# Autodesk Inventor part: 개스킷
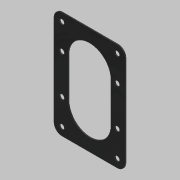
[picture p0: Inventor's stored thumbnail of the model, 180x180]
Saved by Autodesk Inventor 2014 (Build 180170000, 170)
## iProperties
Created: 2019-03
Part Number: 개스킷
Material: 고무
Document SubType Name: Modeling
Designer: mduedu
Density: 1 g/cm^3
Appearance: 고무 - 검은색 - 버전 1.1
Author: mduedu
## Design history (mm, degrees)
sketch "스케치1"
  geometry: L1 (-60, 40)-(60, 40); L2 (60, 40)-(60, -40); L3 (60, -40)-(-60, -40); L4 (-60, -40)-(-60, 40); L5 (-60, 40)-(60, -40); L6 (60, 40)-(-60, -40); 1 further point
  constraints: 12 end point, 2 midpoint, 2 parallel, 1 horizontal, 1 perpendicular
  dimensions: "d21" = 120 distance of L2.end L3.end; "d22" = 80 distance of L1.end L2.end
extrude "돌출1" new body sketch "스케치1" distance "d3" = 1; taper "d4" = 0 deg
fillet "모깎기1" dims "d5" = 9
sketch "스케치2" dims "d6" = 48
  geometry: L1 (-24, -22)-(24, -22); L2 (24, -22)-(24, 22); L3 (24, 22)-(-24, 22); L4 (-24, 22)-(-24, -22); L5 (-24, -22)-(24, 22); L6 (24, -22)-(-24, 22); 3 further points
  constraints: 12 end point, 4 midpoint, 2 horizontal alignment, 2 parallel, 1 horizontal, 1 perpendicular, 4 other
  dimensions: "d8" = 22 distance from line of L3 point (0, 0)
extrude "돌출2" cut sketch "스케치2" stored distance "d9" = 1; taper "d10" = 0 deg
sketch "스케치3"
  geometry: L1 (-24, -22)-(-24, 22) reference; L2 (24, 22)-(24, -22) reference; L3 (40, -51)-(40, 51) reference; L4 (31, 60)-(-31, 60) reference; L5 (-40, 51)-(-40, -51) reference; L6 (-31, -60)-(31, -60) reference; L7 (-31, 51)-(31, 51); L8 (31, 51)-(31, -51); L9 (31, -51)-(-31, -51); L10 (-31, -51)-(-31, 51); A1 r 24 centre (0, 22) between (24, 22) and (-24, 22) reference; A2 r 24 centre (0, -22) between (-24, -22) and (24, -22) reference; A3 r 9 centre (31, -51) between (31, -60) and (40, -51) reference; A4 r 9 centre (31, 51) between (40, 51) and (31, 60) reference; A5 r 9 centre (-31, 51) between (-31, 60) and (-40, 51) reference; A6 r 9 centre (-31, -51) between (-40, -51) and (-31, -60) reference; 9 further points
  constraints: 8 end point, 4 coincident, 4 horizontal alignment, 4 point on line, 2 parallel, 1 horizontal, 1 perpendicular
  dimensions: "d23" = 102 distance between parallel lines of L9 L7 (derived); "d24" = 29 distance from line of point (-31, 22) L7 (derived); "d25" = 29 distance from line of point (-31, -22) L9 (derived)
hole "구멍1" sketch "스케치3" at (-31, 51), (31, 51), (31, -51), (-31, -51), (-31, -22), (-31, 22), (31, 22), (31, -22) diameter "d14" = 5.5; stored, may be unused: countersink angle "d18" = 90 deg, drill point angle "d20" = 118 deg; dims "d15" = 6, "d16" = 4, "d17" = 2, "d19" = 8
node "솔리드1"
node "투영된 루프1"
